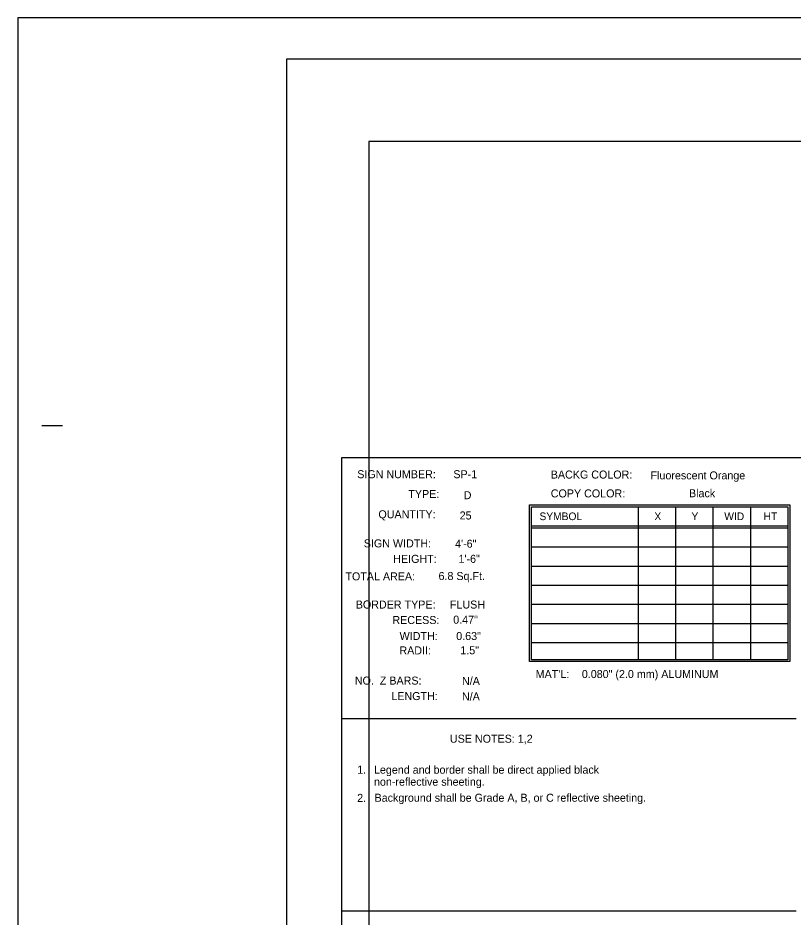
# Model space of a CAD drawing. Extents: x 766449 to 768137, y 650958 to 652521.
# Drawn here: x 766449 to 766920, y 651975 to 652521 of the extents above; entities that cross this region are included whole.
import ezdxf

# ---------------------------------------------------------------- set-up
doc = ezdxf.new("R2010")
doc.units = 0
for name, color, linetype in [('DEV BORDER CELL', 7, 'Continuous'), ('Old_Level_3', 7, 'Continuous'), ('Scratch_Level_0', 7, 'Continuous'), ('Sheet Plot Border Outside CELL', 7, 'Continuous'), ('Text', 7, 'Continuous')]:
    doc.layers.add(name, color=color, linetype=linetype)

msp = doc.modelspace()

# ---------------------------------------------------------------- linework, layer by layer
at = {"layer": 'DEV BORDER CELL'}
for p, q in [((766613.34, 652496.28), (766613.34, 652496.28)), ((766463.84, 652273.78), (766476.34, 652273.78))]:
    msp.add_line(p, q, dxfattribs=at)
msp.add_lwpolyline([(768112.34, 652496.28), (766612.34, 652496.28), (766612.34, 651446.28), (768112.34, 651446.28)], close=True, dxfattribs=at)
at = {"layer": 'Scratch_Level_0'}
msp.add_lwpolyline([(768062.34, 652446.28), (766662.34, 652446.28), (766662.34, 651496.28), (767541.19, 651496.28), (767541.19, 651614.55), (768062.34, 651614.55)], close=True, dxfattribs=at)
at = {"layer": 'Sheet Plot Border Outside CELL'}
msp.add_lwpolyline([(766449.34, 651421.28), (768137.34, 651421.28), (768137.34, 652521.28), (766449.34, 652521.28)], close=True, dxfattribs=at)
at = {"layer": 'Text'}
for p, q in [((766825.84, 652224.37), (766825.84, 652131.49)), ((766848.58, 652224.37), (766848.58, 652131.49)), ((766871.32, 652224.37), (766871.32, 652131.49)), ((766894.06, 652224.37), (766894.06, 652131.49)), ((766761.21, 652212.76), (766916.8, 652212.76)), ((766761.21, 652211.61), (766916.8, 652211.61)), ((766761.21, 652200), (766916.8, 652200)), ((766761.21, 652188.39), (766916.8, 652188.39)), ((766761.21, 652176.78), (766916.8, 652176.78)), ((766761.21, 652165.17), (766916.8, 652165.17)), ((766761.21, 652153.56), (766916.8, 652153.56)), ((766761.21, 652141.95), (766916.8, 652141.95)), ((766921.88, 652095.65), (766646.04, 652095.65)), ((766646.04, 651978.93), (766921.88, 651978.93))]:
    msp.add_line(p, q, dxfattribs=at)
for points in [[(766646.04, 652254.24), (767346.04, 652254.24), (767346.04, 651768.77), (766646.04, 651768.77)], [(766760.01, 652225.54), (766918, 652225.54), (766918, 652130.34), (766760.01, 652130.34)], [(766761.21, 652224.37), (766916.8, 652224.37), (766916.8, 652131.49), (766761.21, 652131.49)]]:
    msp.add_lwpolyline(points, close=True, dxfattribs=at)

# ---------------------------------------------------------------- texts
at = {"layer": 'Old_Level_3'}
for s, height, p in [('SP-1', 4.865, (766713.69, 652241.72)), ('Fluorescent Orange', 4.8646, (766833.43, 652241.01)), ('D', 4.86, (766719.98, 652228.97)), ('25', 4.865, (766717.53, 652216.65)), ('4\'-6"', 4.865, (766714.75, 652199.5)), ('1\'-6"', 4.865, (766716.82, 652190.32)), ('6.8 Sq.Ft.', 4.865, (766704.7, 652179.89)), ('FLUSH', 4.865, (766711.62, 652162.54)), ('0.47"', 4.865, (766713.63, 652153.37)), ('0.63"', 4.865, (766715.45, 652143.43)), ('1.5"', 4.865, (766717.94, 652134.76)), ('N/A', 4.865, (766718.95, 652116.16)), ('N/A', 4.865, (766718.94, 652106.73))]:
    msp.add_text(s, height=height, rotation=360, dxfattribs=at).set_placement(p)
msp.add_text('Black', height=4.865, dxfattribs=at).set_placement((766856.77, 652230.16))
at = {"layer": 'Text'}
for s, height, p in [('SIGN NUMBER:', 4.8646, (766655.35, 652241.72)), ('BACKG COLOR:', 4.8646, (766772.85, 652241.51)), ('COPY COLOR:', 4.8646, (766772.85, 652230.06)), ('TYPE:', 4.865, (766686.37, 652229.71)), ('QUANTITY:', 4.865, (766668.2, 652217.38)), ('SIGN WIDTH:', 4.8646, (766659.3, 652199.7)), ('HEIGHT:', 4.865, (766677.21, 652190.3)), ('TOTAL AREA:', 4.8646, (766648.16, 652179.66)), ('BORDER TYPE:', 4.8646, (766654.44, 652162.56)), ('RECESS:', 4.865, (766676.68, 652153.16)), ('WIDTH:', 4.865, (766681.06, 652143.43)), ('RADII:', 4.865, (766680.94, 652134.68)), ('NO.  Z BARS:', 4.8646, (766653.87, 652116.35)), ("MAT'L:", 4.865, (766763.67, 652120.34)), ('LENGTH:', 4.865, (766676.04, 652106.95)), ('USE NOTES: 1,2', 4.8646, (766711.61, 652081.05)), ('1.', 4.865, (766655.31, 652062.22)), ('Legend and border shall be direct applied black      ', 4.8646, (766665.5, 652062.22)), ('2.', 4.865, (766655.31, 652045.12))]:
    msp.add_text(s, height=height, rotation=360, dxfattribs=at).set_placement(p)
for s, height, p in [('SYMBOL', 4.644, (766766, 652216.26)), ('X', 4.64, (766835.78, 652216.26)), ('Y', 4.64, (766858.28, 652216.26)), ('WID', 4.644, (766878.22, 652216.26)), ('HT', 4.644, (766902.08, 652216.26)), ('0.080" (2.0 mm) ALUMINUM', 4.8646, (766791.71, 652120.34)), ('non-reflective sheeting.', 4.8646, (766665.5, 652054.92)), ('Background shall be Grade A, B, or C reflective sheeting.', 4.8646, (766665.85, 652045.2))]:
    msp.add_text(s, height=height, dxfattribs=at).set_placement(p)

doc.saveas('drawing.dxf')
